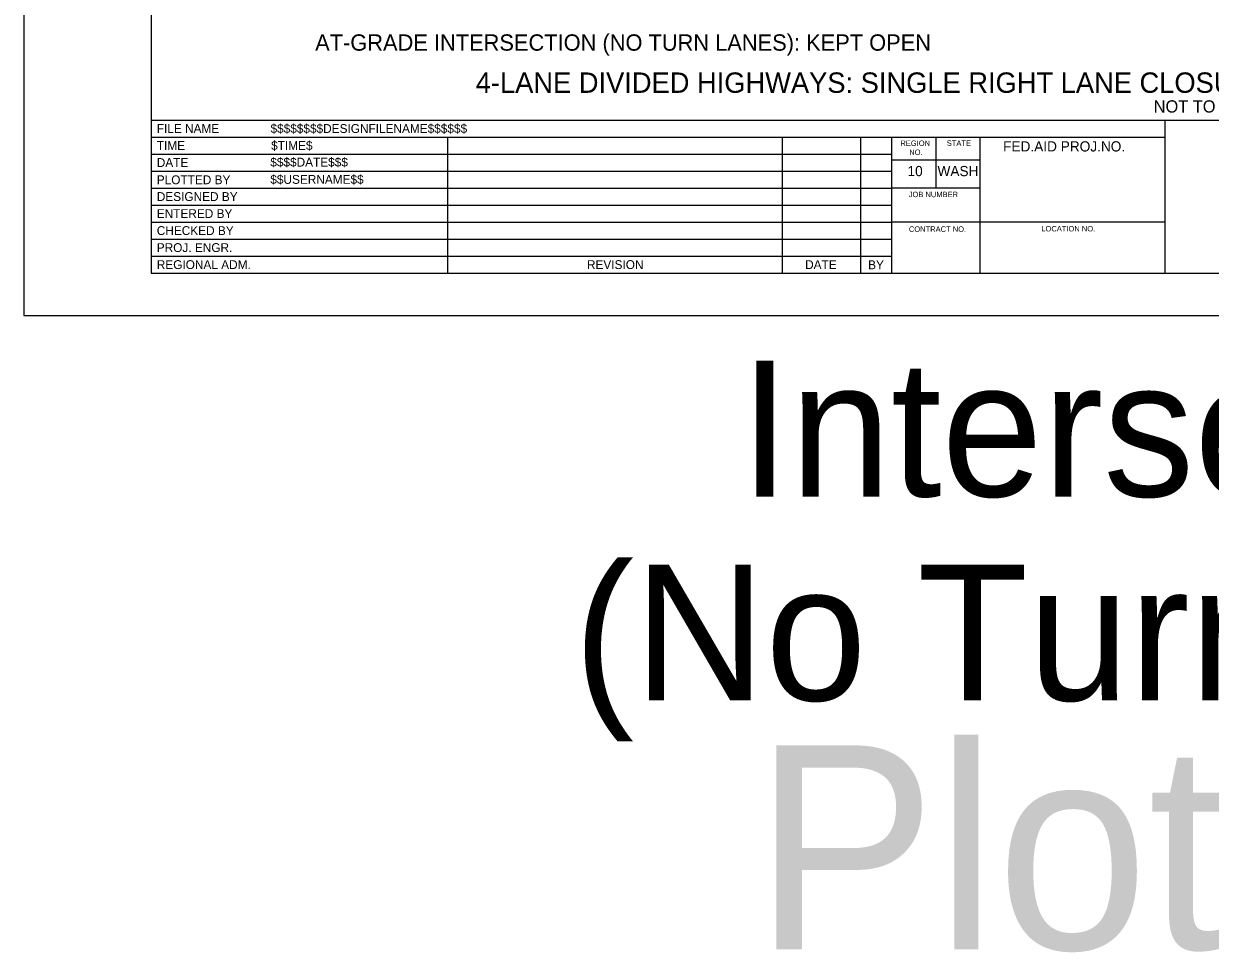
# Model space of a CAD drawing. Extents: x 99958 to 100136, y 99935 to 100013.
# Drawn here: x 100039.06 to 100047.79, y 99965.01 to 99971.83 of the extents above; entities that cross this region are included whole.
import ezdxf

# ---------------------------------------------------------------- set-up
doc = ezdxf.new("R2010")
doc.units = 0
for name, color, linetype in [('SH_DE_DetailHeading1Text', 7, 'Continuous'), ('SH_DE_DetailHeading2Text', 7, 'Continuous'), ('SH_GI_PlotLimits', 7, 'Continuous'), ('SH_GI_SheetBorder', 7, 'Continuous'), ('SH_GI_SheetLocationText', 7, 'Continuous'), ('SH_GI_SheetTextInCells', 7, 'Continuous'), ('SH_GI_TitleBlockText', 7, 'Continuous')]:
    doc.layers.add(name, color=color, linetype=linetype)

msp = doc.modelspace()

# ---------------------------------------------------------------- linework, layer by layer
at = {"layer": 'SH_GI_PlotLimits'}
msp.add_lwpolyline([(100039.0625, 99969.6875), (100056.0625, 99969.6875), (100056.0625, 99980.6875), (100039.0625, 99980.6875)], close=True, dxfattribs=at)
at = {"layer": 'SH_GI_SheetBorder'}
for p, q in [((100040, 99980.375), (100040, 99970)), ((100040, 99971.1259), (100055.75, 99971.1259)), ((100047.4566, 99970), (100047.4566, 99971.1259)), ((100040, 99971.0008), (100047.4566, 99971.0008)), ((100042.179, 99971.0008), (100042.179, 99970)), ((100044.641, 99971.0008), (100044.641, 99970)), ((100045.2164, 99971.0008), (100045.2164, 99970)), ((100045.4451, 99971.0008), (100045.4451, 99970)), ((100045.7719, 99970.6255), (100045.7719, 99971.0008)), ((100046.0956, 99970), (100046.0956, 99971.0008)), ((100040, 99970.8757), (100042.1821, 99970.8757)), ((100042.1821, 99970.8757), (100045.4466, 99970.8757)), ((100046.0958, 99970.831), (100045.4466, 99970.831)), ((100040, 99970.7506), (100042.1821, 99970.7506)), ((100042.1821, 99970.7506), (100045.4466, 99970.7506)), ((100040, 99970.6255), (100045.4466, 99970.6255)), ((100046.0958, 99970.6255), (100045.4466, 99970.6255)), ((100040, 99970.5004), (100045.4466, 99970.5004)), ((100040, 99970.3753), (100045.4466, 99970.3753)), ((100047.4566, 99970.3753), (100045.4466, 99970.3753)), ((100040, 99970.2502), (100045.4466, 99970.2502)), ((100040, 99970.1251), (100045.4466, 99970.1251)), ((100040, 99970), (100055.75, 99970))]:
    msp.add_line(p, q, dxfattribs=at)

# ---------------------------------------------------------------- texts
at = {"layer": 'SH_DE_DetailHeading1Text'}
for s, height, p in [('4-LANE DIVIDED HIGHWAYS: SINGLE RIGHT LANE CLOSURE (45+ MPH, MAINTAIN EXISTING SPEED LIMIT)', 0.15, (100042.3867, 99971.3259)), ('NOT TO SCALE', 0.09, (100047.3727, 99971.1809))]:
    msp.add_text(s, height=height, rotation=360, dxfattribs=at).set_placement(p)
at = {"layer": 'SH_DE_DetailHeading2Text'}
msp.add_text('AT-GRADE INTERSECTION (NO TURN LANES): KEPT OPEN', height=0.12, rotation=360, dxfattribs=at).set_placement((100041.2057, 99971.6359))
at = {"layer": 'SH_GI_SheetLocationText'}
for s, height, p in [('Intersections', 1, (100044.3261, 99968.3571)), ('(No Turn Lanes)', 1, (100043.1065, 99966.8571)), ('Plot 13', 1.5, (100044.4341, 99965.0267))]:
    msp.add_text(s, height=height, dxfattribs=at).set_placement(p)
at = {"layer": 'SH_GI_SheetTextInCells'}
for s, height, p in [('FILE NAME', 0.06505, (100040.041, 99971.0308)), ('TIME', 0.06505, (100040.041, 99970.9057)), ('REGION', 0.04003, (100045.5099, 99970.9352)), ('NO.', 0.04003, (100045.5752, 99970.869)), ('STATE', 0.04003, (100045.8511, 99970.9357)), ('FED.AID PROJ.NO.', 0.07506, (100046.2652, 99970.8945)), ('DATE', 0.06505, (100040.041, 99970.7806)), ('PLOTTED BY', 0.06505, (100040.041, 99970.6538)), ('10', 0.07506, (100045.5621, 99970.7131)), ('WASH', 0.07506, (100045.7826, 99970.7131)), ('DESIGNED BY', 0.065052, (100040.041, 99970.5304)), ('JOB NUMBER', 0.04003, (100045.5712, 99970.5587)), ('ENTERED BY', 0.06505, (100040.041, 99970.4053)), ('CHECKED BY', 0.06505, (100040.041, 99970.2802)), ('CONTRACT NO.', 0.040032, (100045.5725, 99970.3037)), ('LOCATION NO.', 0.040032, (100046.5465, 99970.3067)), ('PROJ. ENGR.', 0.065052, (100040.041, 99970.1551)), ('REGIONAL ADM.', 0.065052, (100040.041, 99970.03)), ('REVISION', 0.06505, (100043.2048, 99970.03)), ('DATE', 0.06505, (100044.8091, 99970.03)), ('BY', 0.06505, (100045.2725, 99970.0285))]:
    msp.add_text(s, height=height, dxfattribs=at).set_placement(p)
at = {"layer": 'SH_GI_TitleBlockText'}
for s, height, p in [('$$$$$$$$DESIGNFILENAME$$$$$$', 0.065052, (100040.8775, 99971.0308)), ('$TIME$', 0.06505, (100040.882, 99970.9059)), ('$$$$DATE$$$', 0.065052, (100040.8759, 99970.7835)), ('$$USERNAME$$', 0.065052, (100040.8759, 99970.6567))]:
    msp.add_text(s, height=height, dxfattribs=at).set_placement(p)

doc.saveas('drawing.dxf')
